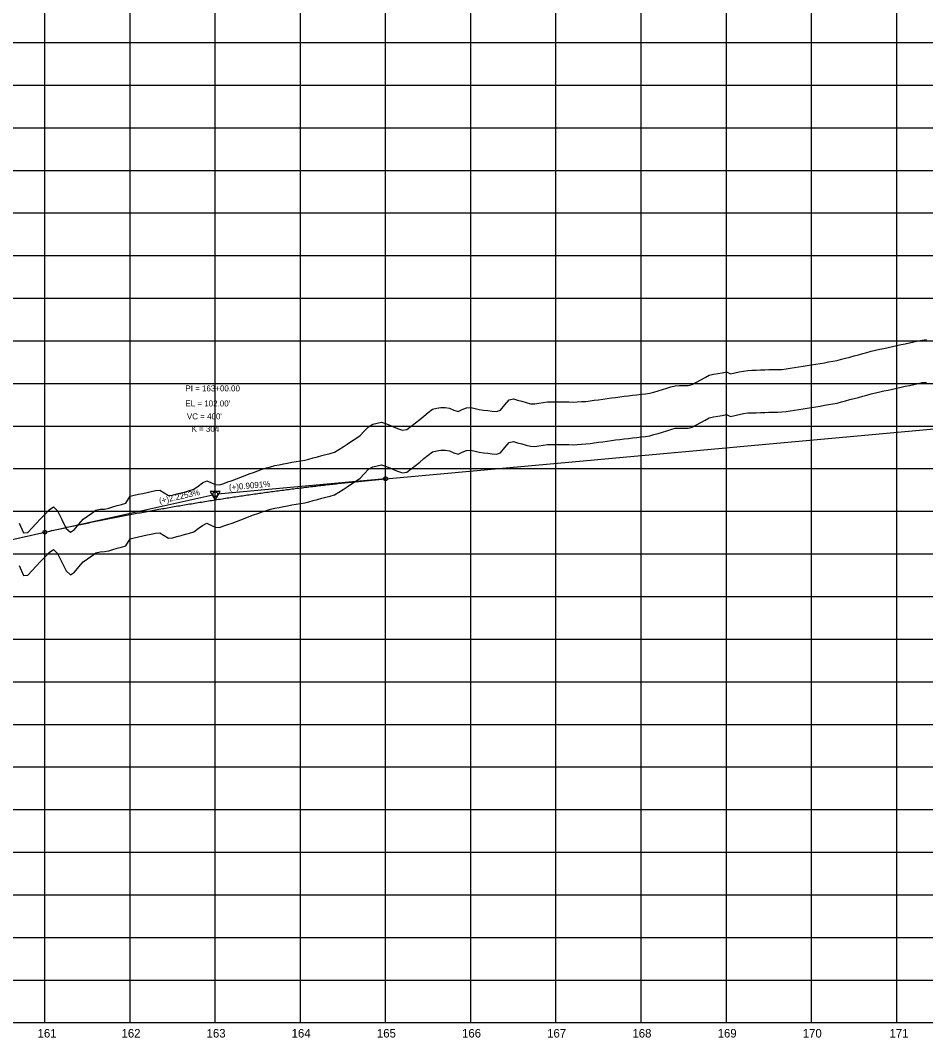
# Model space of a CAD drawing. Extents: x 2345490 to 2436403, y 465165 to 573888.
# Drawn here: x 2396393 to 2397455, y 564259 to 565453 of the extents above; entities that cross this region are included whole.
import ezdxf

# ---------------------------------------------------------------- set-up
doc = ezdxf.new("R2010")
doc.units = 0
for name, color, linetype in [('Old_Level_1', 7, 'Continuous'), ('Old_Level_2', 7, 'Continuous'), ('Old_Level_57', 7, 'Continuous'), ('Old_Level_62', 7, 'Continuous'), ('Old_Level_63', 7, 'Continuous')]:
    doc.layers.add(name, color=color, linetype=linetype)

msp = doc.modelspace()

# ---------------------------------------------------------------- linework, layer by layer
at = {"layer": 'Old_Level_1'}
for points in [[(2397371.5425, 565008.8765), (2397376.5425, 565010.2135), (2397381.5425, 565011.551), (2397386.5425, 565012.8895), (2397391.5425, 565014.2285), (2397396.5425, 565015.50025), (2397401.5425, 565016.59825), (2397406.5425, 565017.697), (2397411.5425, 565018.796), (2397416.5425, 565019.896), (2397421.5425, 565020.99625), (2397426.5425, 565022.09725), (2397431.5425, 565023.19875), (2397436.5425, 565024.30075), (2397441.5425, 565025.40325), (2397446.5425, 565026.4995), (2397451.5425, 565027.46875), (2397456.5425, 565028.1175)], [(2396871.5425, 564942.274), (2396876.5425, 564946.27125), (2396881.5425, 564947.5325), (2396886.5425, 564948.36975), (2396891.5425, 564948.22425), (2396896.5425, 564947.4575), (2396901.5425, 564944.9875), (2396906.5425, 564943.62775), (2396911.5425, 564945.76425), (2396916.5425, 564947.90375), (2396921.5425, 564948.2005), (2396926.5425, 564947.03125), (2396931.5425, 564945.8665), (2396936.5425, 564945.148), (2396941.5425, 564944.604), (2396946.5425, 564944.06375), (2396951.5425, 564943.52725), (2396956.5425, 564945.192), (2396961.5425, 564951.4745), (2396966.5425, 564957.15275), (2396971.5425, 564958.329), (2396976.5425, 564956.93625), (2396981.5425, 564955.54675), (2396986.5425, 564954.16075), (2396991.5425, 564952.77775), (2396996.5425, 564952.68825), (2397001.5425, 564953.484), (2397006.5425, 564954.28125), (2397011.5425, 564954.82525), (2397016.5425, 564954.83175), (2397021.5425, 564954.8395), (2397026.5425, 564954.84875), (2397031.5425, 564954.85925), (2397036.5425, 564954.80125), (2397041.5425, 564954.53975), (2397046.5425, 564954.86125), (2397051.5425, 564955.185), (2397056.5425, 564955.5105), (2397061.5425, 564956.0615), (2397066.5425, 564956.75125), (2397071.5425, 564957.4425), (2397076.5425, 564958.13575), (2397081.5425, 564958.83075), (2397086.5425, 564959.5275), (2397091.5425, 564960.22625), (2397096.5425, 564960.92675), (2397101.5425, 564961.62875), (2397106.5425, 564962.112), (2397111.5425, 564962.63875), (2397116.5425, 564963.2095), (2397121.5425, 564963.781), (2397126.5425, 564964.3535), (2397131.5425, 564964.93475), (2397136.5425, 564966.451), (2397141.5425, 564967.96875), (2397146.5425, 564969.488), (2397151.5425, 564971.009), (2397156.5425, 564972.53125), (2397161.5425, 564973.857), (2397166.5425, 564973.9555), (2397171.5425, 564974.06), (2397176.5425, 564974.16475), (2397181.5425, 564975.24425), (2397186.5425, 564977.9885), (2397191.5425, 564980.734), (2397196.5425, 564983.45175), (2397201.5425, 564986.16275), (2397206.5425, 564987.2385), (2397211.5425, 564988.02), (2397216.5425, 564988.80225), (2397221.5425, 564989.99125), (2397226.5425, 564987.83175), (2397231.5425, 564989.0185), (2397236.5425, 564990.06275), (2397241.5425, 564991.1085), (2397246.5425, 564991.86325), (2397251.5425, 564992.035), (2397256.5425, 564992.20725), (2397261.5425, 564992.3805), (2397266.5425, 564992.5545), (2397271.5425, 564992.729), (2397276.5425, 564992.84325), (2397281.5425, 564992.82825), (2397286.5425, 564993.04425), (2397291.5425, 564993.781), (2397296.5425, 564994.5185), (2397301.5425, 564995.25675), (2397306.5425, 564995.996), (2397311.5425, 564996.736), (2397316.5425, 564997.47675), (2397321.5425, 564998.21825), (2397326.5425, 564998.96075), (2397331.5425, 564999.87975), (2397336.5425, 565000.85575), (2397341.5425, 565001.79475), (2397346.5425, 565002.645), (2397351.5425, 565003.5365), (2397356.5425, 565004.8705), (2397361.5425, 565006.205), (2397366.5425, 565007.5405), (2397371.5425, 565008.8765)], [(2396391.5425, 564812.7395), (2396396.5425, 564801.323), (2396401.5425, 564801.66625), (2396406.5425, 564806.9515), (2396411.5425, 564812.239), (2396416.5425, 564817.529), (2396421.5425, 564822.8215), (2396426.5425, 564828.11625), (2396431.5425, 564831.665), (2396436.5425, 564827.17725), (2396441.5425, 564816.8385), (2396446.5425, 564806.5055), (2396451.5425, 564802.0505), (2396456.5425, 564805.1195), (2396461.5425, 564811.28725), (2396466.5425, 564817.27225), (2396471.5425, 564820.7955), (2396476.5425, 564824.321), (2396481.5425, 564827.8485), (2396486.5425, 564828.9995), (2396491.5425, 564829.1725), (2396496.5425, 564830.183), (2396501.5425, 564831.64825), (2396506.5425, 564833.1215), (2396511.5425, 564834.60325), (2396516.5425, 564836.09325), (2396521.5425, 564844.14225), (2396526.5425, 564845.28575), (2396531.5425, 564846.429), (2396536.5425, 564847.5725), (2396541.5425, 564848.71625), (2396546.5425, 564849.85975), (2396551.5425, 564851.0035), (2396556.5425, 564851.4305), (2396561.5425, 564848.2085), (2396566.5425, 564844.995), (2396571.5425, 564845.5455), (2396576.5425, 564846.8515), (2396581.5425, 564848.16775), (2396586.5425, 564849.49425), (2396591.5425, 564850.8315), (2396596.5425, 564852.5395), (2396601.5425, 564856.1645), (2396606.5425, 564859.79125), (2396611.5425, 564862.40575), (2396616.5425, 564860.2005), (2396621.5425, 564857.8605), (2396626.5425, 564857.544), (2396631.5425, 564859.275), (2396636.5425, 564861.008), (2396641.5425, 564862.7425), (2396646.5425, 564864.60325), (2396651.5425, 564866.4955), (2396656.5425, 564868.38775), (2396661.5425, 564870.28), (2396666.5425, 564872.172), (2396671.5425, 564874.06425), (2396676.5425, 564875.95625), (2396681.5425, 564877.518), (2396686.5425, 564878.8225), (2396691.5425, 564880.0945), (2396696.5425, 564881.08325), (2396701.5425, 564882.071), (2396706.5425, 564883.05825), (2396711.5425, 564883.97175), (2396716.5425, 564884.78325), (2396721.5425, 564885.594), (2396726.5425, 564886.404), (2396731.5425, 564887.79625), (2396736.5425, 564889.23125), (2396741.5425, 564890.5355), (2396746.5425, 564891.838), (2396751.5425, 564893.13925), (2396756.5425, 564894.43875), (2396761.5425, 564895.737), (2396766.5425, 564898.93675), (2396771.5425, 564902.16525), (2396776.5425, 564905.4015), (2396781.5425, 564908.64525), (2396786.5425, 564911.89625), (2396791.5425, 564915.28525), (2396796.5425, 564920.54075), (2396801.5425, 564925.80425), (2396806.5425, 564928.726), (2396811.5425, 564929.896), (2396816.5425, 564931.039), (2396821.5425, 564929.57075), (2396826.5425, 564927.4465), (2396831.5425, 564925.3235), (2396836.5425, 564923.324), (2396841.5425, 564921.83175), (2396846.5425, 564922.3), (2396851.5425, 564926.29325), (2396856.5425, 564930.28725), (2396861.5425, 564934.282), (2396866.5425, 564938.2775), (2396871.5425, 564942.274)]]:
    msp.add_lwpolyline(points, dxfattribs=at)
at = {"layer": 'Old_Level_2'}
for p, q in [((2396821.5425, 564914.71575), (2398621.5425, 565078.352)), ((2396821.5425, 564914.71575), (2396624.28125, 564896.78275)), ((2396421.5425, 564852.02725), (2396618.85825, 564895.9365)), ((2396221.5425, 564807.5205), (2396421.5425, 564852.02725))]:
    msp.add_line(p, q, dxfattribs=at)
msp.add_lwpolyline([(2396627.299, 564899.86625), (2396615.5565, 564899.85175), (2396621.44, 564889.7335)], close=True, dxfattribs=at)
for centre, radius in [((2396821.5425, 564914.71575), 2.25), ((2396621.5425, 564896.534), 2.75), ((2396421.5425, 564852.02725), 2.25)]:
    msp.add_circle(centre, radius, dxfattribs=at)
msp.add_spline([(2396421.5425, 564852.02725), (2396429.5425, 564853.797), (2396437.5425, 564855.5455), (2396445.5425, 564857.27325), (2396453.5425, 564858.97975), (2396461.5425, 564860.66525), (2396469.5425, 564862.32975), (2396477.5425, 564863.973), (2396485.5425, 564865.5955), (2396493.5425, 564867.19675), (2396501.5425, 564868.777), (2396509.5425, 564870.336), (2396517.5425, 564871.874), (2396525.5425, 564873.391), (2396533.5425, 564874.887), (2396541.5425, 564876.362), (2396549.5425, 564877.81575), (2396557.5425, 564879.2485), (2396565.5425, 564880.66025), (2396573.5425, 564882.051), (2396581.5425, 564883.4205), (2396589.5425, 564884.769), (2396597.5425, 564886.0965), (2396605.5425, 564887.403), (2396613.5425, 564888.68825), (2396621.5425, 564889.95275), (2396629.5425, 564891.196), (2396637.5425, 564892.418), (2396645.5425, 564893.61925), (2396653.5425, 564894.79925), (2396661.5425, 564895.95825), (2396669.5425, 564897.09625), (2396677.5425, 564898.213), (2396685.5425, 564899.309), (2396693.5425, 564900.38375), (2396701.5425, 564901.43725), (2396709.5425, 564902.47), (2396717.5425, 564903.4815), (2396725.5425, 564904.472), (2396733.5425, 564905.4415), (2396741.5425, 564906.39), (2396749.5425, 564907.31725), (2396757.5425, 564908.2235), (2396765.5425, 564909.10875), (2396773.5425, 564909.973), (2396781.5425, 564910.816), (2396789.5425, 564911.638), (2396797.5425, 564912.439), (2396805.5425, 564913.219), (2396813.5425, 564913.978), (2396821.5425, 564914.71575)], degree=3, dxfattribs=at)
at = {"layer": 'Old_Level_57'}
for p, q in [((2396421.54225, 564276.534), (2396421.54225, 566615.2835)), ((2396521.54225, 564276.534), (2396521.54225, 566615.2835)), ((2396621.54225, 564276.534), (2396621.54225, 566615.2835)), ((2396721.54225, 564276.534), (2396721.54225, 566615.2835)), ((2396821.54225, 564276.534), (2396821.54225, 566615.2835)), ((2396921.54225, 564276.534), (2396921.54225, 566615.2835)), ((2397021.54225, 564276.534), (2397021.54225, 566615.2835)), ((2397121.54225, 564276.534), (2397121.54225, 566615.2835)), ((2397221.54225, 564276.534), (2397221.54225, 566615.2835)), ((2397321.5425, 564276.534), (2397321.5425, 566615.2835)), ((2397421.54225, 564276.534), (2397421.54225, 566615.2835)), ((2381271.5425, 565426.534), (2410861.12275, 565426.534)), ((2381271.5425, 565376.534), (2410861.12275, 565376.534)), ((2381271.5425, 565326.534), (2410861.12275, 565326.534)), ((2381271.5425, 565276.534), (2410861.12275, 565276.534)), ((2381271.5425, 565226.534), (2410861.12275, 565226.534)), ((2381271.5425, 565176.534), (2410861.12275, 565176.534)), ((2381271.5425, 565126.534), (2410861.12275, 565126.534)), ((2381271.5425, 565076.534), (2410861.12275, 565076.534)), ((2381271.5425, 565026.534), (2410861.12275, 565026.534)), ((2381271.5425, 564976.534), (2410861.12275, 564976.534)), ((2381271.5425, 564926.534), (2410861.12275, 564926.534)), ((2381271.5425, 564876.534), (2410861.12275, 564876.534)), ((2381271.5425, 564826.534), (2410861.12275, 564826.534)), ((2381271.54275, 564776.534), (2410861.123, 564776.534)), ((2381271.5425, 564726.534), (2410861.12275, 564726.534)), ((2381271.54275, 564676.534), (2410861.123, 564676.534)), ((2381271.5425, 564626.534), (2410861.12275, 564626.534)), ((2381271.54275, 564576.534), (2410861.123, 564576.534)), ((2381271.5425, 564526.534), (2410861.12275, 564526.534)), ((2381271.54275, 564476.534), (2410861.123, 564476.534)), ((2381271.5425, 564426.534), (2410861.12275, 564426.534)), ((2381271.54275, 564376.534), (2410861.123, 564376.534)), ((2381271.5425, 564326.534), (2410861.12275, 564326.534)), ((2381271.54275, 564276.534), (2410861.123, 564276.534))]:
    msp.add_line(p, q, dxfattribs=at)
at = {"layer": 'Old_Level_63'}
msp.add_line((2381321.5425, 564276.534), (2406689.937, 564276.534), dxfattribs=at)
for points in [[(2397371.5425, 565058.87625), (2397376.5425, 565060.21325), (2397381.5425, 565061.55075), (2397386.5425, 565062.88925), (2397391.5425, 565064.22825), (2397396.5425, 565065.5), (2397401.5425, 565066.598), (2397406.5425, 565067.69675), (2397411.5425, 565068.79575), (2397416.5425, 565069.89575), (2397421.5425, 565070.996), (2397426.5425, 565072.097), (2397431.5425, 565073.1985), (2397436.5425, 565074.3005), (2397441.5425, 565075.403), (2397446.5425, 565076.49925), (2397451.5425, 565077.4685), (2397456.5425, 565078.11725)], [(2396871.5425, 564992.27375), (2396876.5425, 564996.271), (2396881.5425, 564997.53225), (2396886.5425, 564998.3695), (2396891.5425, 564998.224), (2396896.5425, 564997.45725), (2396901.5425, 564994.98725), (2396906.5425, 564993.6275), (2396911.5425, 564995.764), (2396916.5425, 564997.9035), (2396921.5425, 564998.20025), (2396926.5425, 564997.031), (2396931.5425, 564995.86625), (2396936.5425, 564995.14775), (2396941.5425, 564994.60375), (2396946.5425, 564994.0635), (2396951.5425, 564993.527), (2396956.5425, 564995.19175), (2396961.5425, 565001.47425), (2396966.5425, 565007.1525), (2396971.5425, 565008.32875), (2396976.5425, 565006.936), (2396981.5425, 565005.5465), (2396986.5425, 565004.1605), (2396991.5425, 565002.7775), (2396996.5425, 565002.688), (2397001.5425, 565003.48375), (2397006.5425, 565004.281), (2397011.5425, 565004.825), (2397016.5425, 565004.8315), (2397021.5425, 565004.83925), (2397026.5425, 565004.8485), (2397031.5425, 565004.859), (2397036.5425, 565004.801), (2397041.5425, 565004.5395), (2397046.5425, 565004.861), (2397051.5425, 565005.18475), (2397056.5425, 565005.51025), (2397061.5425, 565006.06125), (2397066.5425, 565006.751), (2397071.5425, 565007.44225), (2397076.5425, 565008.1355), (2397081.5425, 565008.8305), (2397086.5425, 565009.52725), (2397091.5425, 565010.226), (2397096.5425, 565010.9265), (2397101.5425, 565011.6285), (2397106.5425, 565012.11175), (2397111.5425, 565012.6385), (2397116.5425, 565013.20925), (2397121.5425, 565013.78075), (2397126.5425, 565014.35325), (2397131.5425, 565014.9345), (2397136.5425, 565016.45075), (2397141.5425, 565017.9685), (2397146.5425, 565019.48775), (2397151.5425, 565021.00875), (2397156.5425, 565022.531), (2397161.5425, 565023.85675), (2397166.5425, 565023.95525), (2397171.5425, 565024.05975), (2397176.5425, 565024.1645), (2397181.5425, 565025.244), (2397186.5425, 565027.98825), (2397191.5425, 565030.73375), (2397196.5425, 565033.4515), (2397201.5425, 565036.1625), (2397206.5425, 565037.23825), (2397211.5425, 565038.01975), (2397216.5425, 565038.802), (2397221.5425, 565039.991), (2397226.5425, 565037.8315), (2397231.5425, 565039.01825), (2397236.5425, 565040.0625), (2397241.5425, 565041.10825), (2397246.5425, 565041.863), (2397251.5425, 565042.03475), (2397256.5425, 565042.207), (2397261.5425, 565042.38025), (2397266.5425, 565042.55425), (2397271.5425, 565042.72875), (2397276.5425, 565042.843), (2397281.5425, 565042.828), (2397286.5425, 565043.044), (2397291.5425, 565043.78075), (2397296.5425, 565044.51825), (2397301.5425, 565045.2565), (2397306.5425, 565045.99575), (2397311.5425, 565046.73575), (2397316.5425, 565047.4765), (2397321.5425, 565048.218), (2397326.5425, 565048.9605), (2397331.5425, 565049.8795), (2397336.5425, 565050.8555), (2397341.5425, 565051.7945), (2397346.5425, 565052.64475), (2397351.5425, 565053.53625), (2397356.5425, 565054.87025), (2397361.5425, 565056.20475), (2397366.5425, 565057.54025), (2397371.5425, 565058.87625)], [(2396391.5425, 564862.73925), (2396396.5425, 564851.32275), (2396401.5425, 564851.666), (2396406.5425, 564856.95125), (2396411.5425, 564862.23875), (2396416.5425, 564867.52875), (2396421.5425, 564872.82125), (2396426.5425, 564878.116), (2396431.5425, 564881.66475), (2396436.5425, 564877.177), (2396441.5425, 564866.83825), (2396446.5425, 564856.50525), (2396451.5425, 564852.05025), (2396456.5425, 564855.11925), (2396461.5425, 564861.287), (2396466.5425, 564867.272), (2396471.5425, 564870.79525), (2396476.5425, 564874.32075), (2396481.5425, 564877.84825), (2396486.5425, 564878.99925), (2396491.5425, 564879.17225), (2396496.5425, 564880.18275), (2396501.5425, 564881.648), (2396506.5425, 564883.12125), (2396511.5425, 564884.603), (2396516.5425, 564886.093), (2396521.5425, 564894.142), (2396526.5425, 564895.2855), (2396531.5425, 564896.42875), (2396536.5425, 564897.57225), (2396541.5425, 564898.716), (2396546.5425, 564899.8595), (2396551.5425, 564901.00325), (2396556.5425, 564901.43025), (2396561.5425, 564898.20825), (2396566.5425, 564894.99475), (2396571.5425, 564895.54525), (2396576.5425, 564896.85125), (2396581.5425, 564898.1675), (2396586.5425, 564899.494), (2396591.5425, 564900.83125), (2396596.5425, 564902.53925), (2396601.5425, 564906.16425), (2396606.5425, 564909.791), (2396611.5425, 564912.4055), (2396616.5425, 564910.20025), (2396621.5425, 564907.86025), (2396626.5425, 564907.54375), (2396631.5425, 564909.27475), (2396636.5425, 564911.00775), (2396641.5425, 564912.74225), (2396646.5425, 564914.603), (2396651.5425, 564916.49525), (2396656.5425, 564918.3875), (2396661.5425, 564920.27975), (2396666.5425, 564922.17175), (2396671.5425, 564924.064), (2396676.5425, 564925.956), (2396681.5425, 564927.51775), (2396686.5425, 564928.82225), (2396691.5425, 564930.09425), (2396696.5425, 564931.083), (2396701.5425, 564932.07075), (2396706.5425, 564933.058), (2396711.5425, 564933.9715), (2396716.5425, 564934.783), (2396721.5425, 564935.59375), (2396726.5425, 564936.40375), (2396731.5425, 564937.796), (2396736.5425, 564939.231), (2396741.5425, 564940.53525), (2396746.5425, 564941.83775), (2396751.5425, 564943.139), (2396756.5425, 564944.4385), (2396761.5425, 564945.73675), (2396766.5425, 564948.9365), (2396771.5425, 564952.165), (2396776.5425, 564955.40125), (2396781.5425, 564958.645), (2396786.5425, 564961.896), (2396791.5425, 564965.285), (2396796.5425, 564970.5405), (2396801.5425, 564975.804), (2396806.5425, 564978.72575), (2396811.5425, 564979.89575), (2396816.5425, 564981.03875), (2396821.5425, 564979.5705), (2396826.5425, 564977.44625), (2396831.5425, 564975.32325), (2396836.5425, 564973.32375), (2396841.5425, 564971.8315), (2396846.5425, 564972.29975), (2396851.5425, 564976.293), (2396856.5425, 564980.287), (2396861.5425, 564984.28175), (2396866.5425, 564988.27725), (2396871.5425, 564992.27375)]]:
    msp.add_lwpolyline(points, dxfattribs=at)

# ---------------------------------------------------------------- texts
at = {"layer": 'Old_Level_2'}
for s, height, p in [('PI = 163+00.00', 7.0000005, (2396586.54275, 565017.2145)), ("EL = 102.00'", 7.0000005, (2396586.5425, 564999.534)), ("VC = 400'", 7.000001, (2396588.3075, 564984.35075)), ('K = 304', 7.000001, (2396593.718, 564969.7455))]:
    msp.add_text(s, height=height, dxfattribs=at).set_placement(p)
for s, rotation, p in [('(+)0.9091%', 5.19442778, (2396638.00175, 564901.04225)), ('(+)2.2253%', 12.54579444, (2396556.45625, 564885.12325))]:
    msp.add_text(s, height=7.000001, rotation=rotation, dxfattribs=at).set_placement(p)
at = {"layer": 'Old_Level_62'}
for s, p in [('161', (2396413.01075, 564259.034)), ('162', (2396511.55925, 564259.034)), ('163', (2396611.394, 564259.034)), ('164', (2396711.2365, 564259.034)), ('165', (2396811.329, 564259.034)), ('166', (2396911.27, 564259.034)), ('167', (2397011.1275, 564259.034)), ('168', (2397111.25325, 564259.034)), ('169', (2397211.2955, 564259.034)), ('170', (2397311.1715, 564259.034)), ('171', (2397413.01075, 564259.034))]:
    msp.add_text(s, height=10.000001, dxfattribs=at).set_placement(p)

doc.saveas('drawing.dxf')
